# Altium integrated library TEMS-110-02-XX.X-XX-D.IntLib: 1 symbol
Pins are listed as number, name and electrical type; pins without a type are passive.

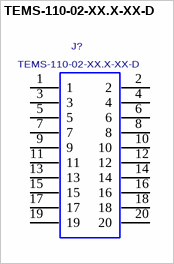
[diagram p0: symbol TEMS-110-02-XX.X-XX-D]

## TEMS-110-02-XX.X-XX-D
designator J?
0.8MM TIGER EYE MICRO TERMINAL, 20 PINS.; MANUFACTURER: SAMTEC
footprint TEMS-110-02-XX.X-XX-D
pins: 1, 2, 3, 4, 5, 6, 7, 8, 9, 10, 11, 12, 13, 14, 15, 16, 17, 18, 19, 20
